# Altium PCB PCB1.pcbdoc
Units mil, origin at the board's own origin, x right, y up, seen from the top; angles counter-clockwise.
Board outline 4493.1 x 3021.15 mil, 2 copper layers (Top Layer, Bottom Layer); 85 components, 97 nets, 410 pads, 224 vias.
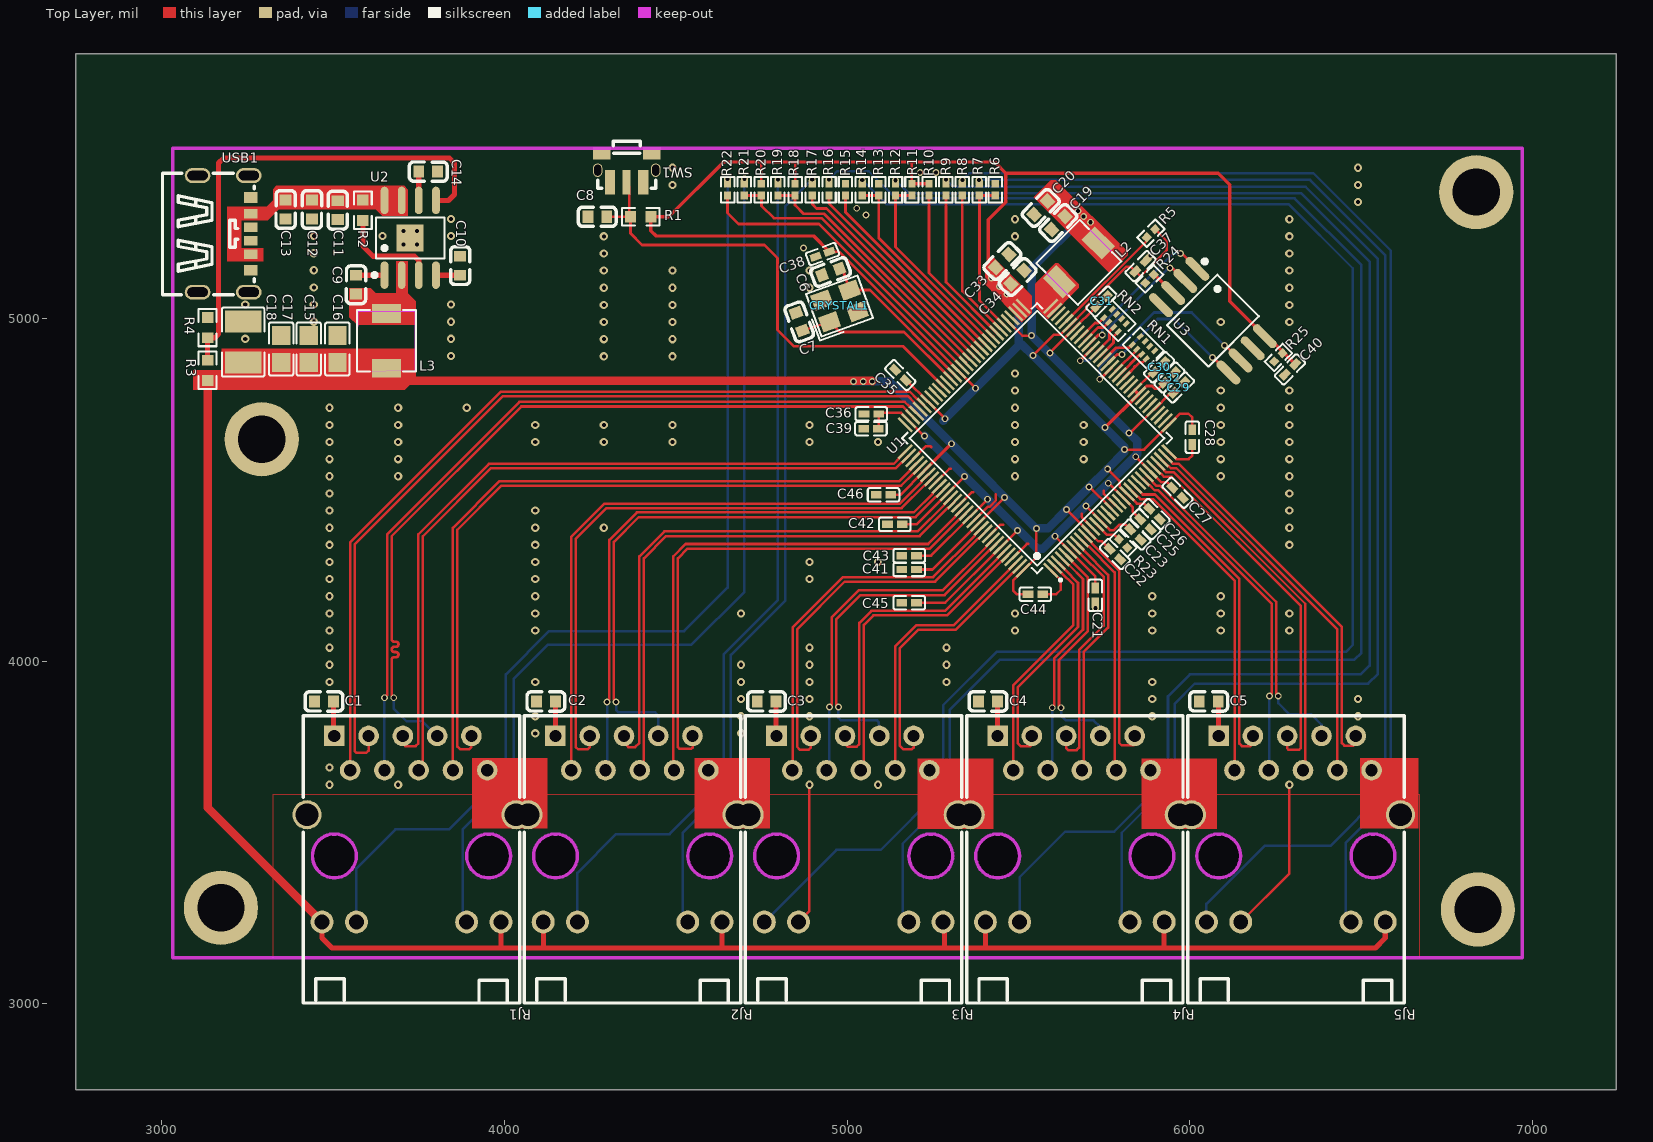
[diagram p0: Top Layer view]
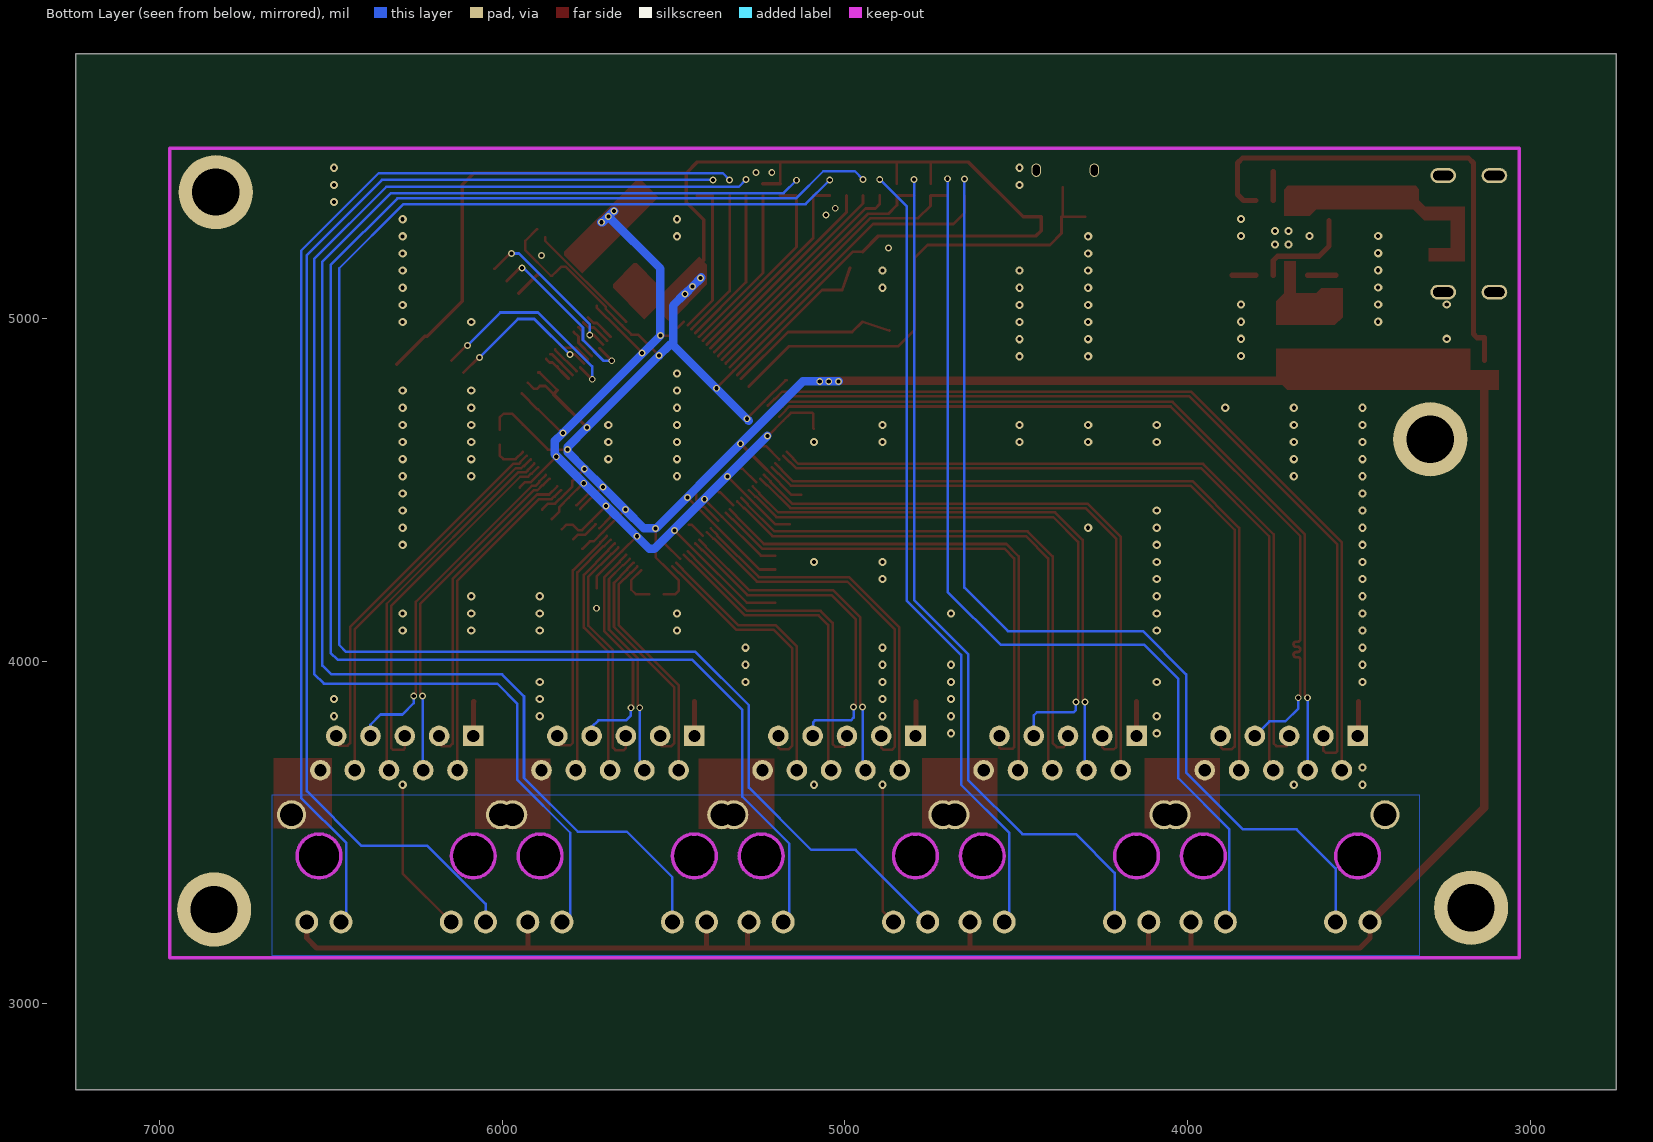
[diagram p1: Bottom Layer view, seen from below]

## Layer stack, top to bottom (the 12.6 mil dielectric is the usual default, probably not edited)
Top Layer: signal copper (thickness not stored)
Dielectric: dielectric 12.6, FR-4, Dk 4.8
Bottom Layer: signal copper (thickness not stored)

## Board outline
7243.1,2750 2750,2750 2750,5771.15 7243.1,5771.15

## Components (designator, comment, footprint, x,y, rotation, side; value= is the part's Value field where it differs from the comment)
C1 "CAP_0603" C0603 3473.85,3882.04 r0 top
C2 "CAP_0603" C0603 4121.23,3882.04 r0 top
C3 "CAP_0603" C0603 4764.99,3882.04 r0 top
C4 "CAP_0603" C0603 5410.99,3882.04 r0 top
C5 "CAP_0603" C0603 6054.99,3882.04 r0 top
C6 "CAP_0603" C0603 4951.99,5135.04 r20 top
C7 "CAP_0603" C0603 4859.99,4990.04 r110 top
C8 "CAP_0603" C0603 4270.99,5296 r0 top
C9 "CAP_0603" C0603 3567.16,5098.04 r90 top
C10 "CAP_0603" C0603 3870.84,5153.3 r270 top
C11 "CAP_0603" C0603 3513.66,5315.46 r90 top
C12 "CAP_0603" C0603 3438.72,5317.52 r90 top
C13 "CAP_0603" C0603 3361.72,5317.52 r90 top
C14 "CAP_0603" C0603 3777.55,5428.04 r180 top
C15 "CAP_0805" C0805 3429.16,4910.31 r270 top
C16 "CAP_0805" C0805 3512.7,4910.31 r270 top
C17 "CAP_0805" C0805 3348.7,4910.31 r270 top
C18 "JMK325ABJ107MM-T" C1210 3237.7,4930.68 r270 top
C19 "CAP_0603" C0603 5615.99,5278.04 r45 top
C20 "CAP_0603" C0603 5564.99,5322.04 r45 top
C21 "CAP_0402" C0402 5723.99,4191.55 r270 top
C22 "CAP_0402" C0402 5780.99,4312.04 r315 top
C23 "CAP_0402" C0402 5840.99,4369.04 r315 top
C25 "CAP_0402" C0402 5869.99,4399.21 r315 top
C26 "CAP_0402" C0402 5896.99,4429.04 r315 top
C27 "CAP_0402" C0402 5963.99,4491.04 r315 top
C28 "CAP_0402" C0402 6006.99,4653.04 r270 top
C29 "CAP_0402" C0402 5967.99,4798.04 r45 top
C30 "CAP_0402" C0402 5909.99,4857.04 r45 top
C31 "CAP_0402" C0402 5741.99,5049.04 r45 top
C32 "CAP_0402" C0402 5939.99,4827.04 r45 top
C33 "CAP_0603" C0603 5452.38,5167.04 r225 top
C34 "CAP_0603" C0603 5496.92,5120.04 r225 top
C35 "CAP_0402" C0402 5154.99,4834.04 r135 top
C36 "CAP_0402" C0402 5070.37,4721.04 r180 top
C37 "CAP_0402" C0402 5855.99,5152.04 r45 top
C38 "CAP_0402" C0402 4927.99,5187.04 r200 top
C39 "CAP_0402" C0402 5069.34,4678.04 r180 top
C40 "CAP_0402" C0402 6291.99,4851.04 r45 top
C41 "CAP_0402" C0402 5180.92,4267.04 r180 top
C42 "CAP_0402" C0402 5139.01,4398.98 r180 top
C43 "CAP_0402" C0402 5180.92,4307.57 r180 top
C44 "CAP_0402" C0402 5548.98,4195.04 r0 top
C45 "CAP_0402" C0402 5180.92,4170.04 r180 top
C46 "CAP_0402" C0402 5105.99,4485.04 r180 top
CRYSTAL1 "CF4025M00010" CRYSTAL-SMD_4P-L3.2-W2.5-BL 4977.99,5036.04 r20 top
L2 "FXL0420-2R2-M" IND-SMD_L4.4-W4.2 5675.99,5163.04 r225 top
L3 "FXL0420-2R2-M" IND-SMD_L4.4-W4.2 3655.99,4934.15 r270 top
R1 "Res_0603" R0603 4397.71,5296.11 r0 top
R2 "Res_0603" R0603 3586.96,5315.04 r90 top
R3 "Res_0603" R0603 3134.16,4848.04 r270 top
R4 "Res_0603" R0603 3134.16,4972.97 r270 top
R5 "Res_0402" R0402 5885.99,5248.04 r225 top
R6 "Res_0402" R0402 5431.99,5375.33 r270 top
R7 "Res_0402" R0402 5384.99,5375.33 r270 top
R8 "Res_0402" R0402 5335.99,5375.33 r270 top
R9 "Res_0402" R0402 5287.99,5375.33 r270 top
R10 "Res_0402" R0402 5238.99,5375.33 r270 top
R11 "Res_0402" R0402 5188.99,5375.33 r270 top
R12 "Res_0402" R0402 5140.99,5375.33 r270 top
R13 "Res_0402" R0402 5091.99,5375.33 r270 top
R14 "Res_0402" R0402 5043.99,5375.33 r270 top
R15 "Res_0402" R0402 4994.99,5375.33 r270 top
R16 "Res_0402" R0402 4946.99,5375.33 r270 top
R17 "Res_0402" R0402 4897.99,5375.33 r270 top
R18 "Res_0402" R0402 4847.99,5375.33 r270 top
R19 "Res_0402" R0402 4797.99,5375.33 r270 top
R20 "Res_0402" R0402 4748.99,5375.33 r270 top
R21 "Res_0402" R0402 4699.99,5375.33 r270 top
R22 "Res_0402" R0402 4650.99,5375.33 r270 top
R23 "Res_0402" R0402 5804.99,4343.04 r135 top
R24 "Res_0402" R0402 5881.99,5115.04 r45 top
R25 "Res_0402" R0402 6257.99,4886.04 r45 top
RJ1 "HR911130A" RJ45-TH_HR911130A 3728.99,3510.04 r180 top
RJ2 "HR911130A" RJ45-TH_HR911130A 4373.99,3510.04 r180 top
RJ3 "HR911130A" RJ45-TH_HR911130A 5018.99,3510.04 r180 top
RJ4 "HR911130A" RJ45-TH_HR911130A 5663.99,3510.04 r180 top
RJ5 "HR911130A" RJ45-TH_HR911130A 6308.99,3510.04 r180 top
RN1 "EXB28V102JX" RES-ARRAY-SMD_0402-8P-L2.0-W1.0-BL 5863.99,4914.04 r135 top
RN2 "EXB28V102JX" RES-ARRAY-SMD_0402-8P-L2.0-W1.0-BL 5781.99,4993.04 r135 top
SW1 "ST-1133" KEY-SMD_ST-1133 4356.71,5439.04 r180 top
U1 "RTL8367S-CG" LQFP-128_L14.0-W14.0-P0.40-LS16.0-BL 5553.99,4650.04 r45 top
U2 "SY8205FCC" SOIC-8_L5.0-W4.0-P1.27-LS6.0-BL-EP2.0 3725.16,5234.76 r0 top
U3 "W25Q32JVSSIQ" SOIC-8_L5.3-W5.3-P1.27-LS8.0-BL 6066.99,4993.04 r225 top
USB1 "TYPE-C 6P(073)" TYPE-C-SMD_TYPE-C-6P 3181.99,5246.23 r270 top

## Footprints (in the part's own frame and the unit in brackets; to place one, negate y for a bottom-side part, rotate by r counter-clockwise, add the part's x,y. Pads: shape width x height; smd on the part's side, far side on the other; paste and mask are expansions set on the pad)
C0402 [mm]
  rect 0.79x0.54 smd: 1(-0.545,0) 2(0.545,0)
  silkscreen extent -1.17,-0.5 1.17,0.5
C0603 [mm]
  rect 0.8x0.9 smd: 1(-0.7,0) 2(0.7,0)
  silkscreen extent -1.41,-0.71 1.39,0.72
C0805 [mm]
  rect 1.41x1.35 smd: 1(-1,0) 2(1,0)
  silkscreen extent -1.96,-0.9 1.96,0.9
C1210 [mm]
  rect 1.635x2.7 smd: 1(-1.517,0) 2(1.517,0)
  silkscreen extent -2.56,-1.58 2.56,1.58
CRYSTAL-SMD_4P-L3.2-W2.5-BL [mm]
  rect 1.4x1.2 smd: 1(-1.1,-0.85) 2(1.1,-0.85) 3(1.1,0.85) 4(-1.1,0.85)
  silkscreen extent -2.26,-1.91 2.03,1.68
IND-SMD_L4.4-W4.2 [mm]
  rect 1.4x2.12 smd: 1(2.028,0) 2(-2.028,0)
  silkscreen extent -2.28,-2.18 2.28,2.18
KEY-SMD_ST-1133 [mm]
  oval 0.7x1 hole 0.5 slot 0.8 at 90 deg: 1(-2.15,0.175) 3(2.15,0.175)
  rect 1.3x0.9 smd: 1(-1.85,-1.075) 3(1.85,-1.075)
  rect 0.75x1.8 smd: 1(-1.225,1.075) 3(1.225,1.075)
  rect 0.6x1.8 smd: 2(0,1.075)
  silkscreen extent -2.16,-1.96 2.16,1.52
LQFP-128_L14.0-W14.0-P0.40-LS16.0-BL [mm]
  rect 0.2x1.46 smd: 1(-6.2,-7.63) 2(-5.8,-7.63) 3(-5.4,-7.63) 4(-5,-7.63) 5(-4.6,-7.63) 6(-4.2,-7.63) 7(-3.8,-7.63) 8(-3.4,-7.63) 9(-3,-7.63) 10(-2.6,-7.63) 11(-2.2,-7.63) 12(-1.8,-7.63) 13(-1.4,-7.63) 14(-1,-7.63) 15(-0.6,-7.63) 16(-0.2,-7.63) 17(0.2,-7.63) 18(0.6,-7.63) 19(1,-7.63) 20(1.4,-7.63) 21(1.8,-7.63) 22(2.2,-7.63) 23(2.6,-7.63) 24(3,-7.63) 25(3.4,-7.63) 26(3.8,-7.63) 27(4.2,-7.63) 28(4.6,-7.63) 29(5,-7.63) 30(5.4,-7.63) 31(5.8,-7.63) 32(6.2,-7.63) 65(6.2,7.63) 66(5.8,7.63) 67(5.4,7.63) 68(5,7.63) 69(4.6,7.63) 70(4.2,7.63) 71(3.8,7.63) 72(3.4,7.63) 73(3,7.63) 74(2.6,7.63) 75(2.2,7.63) 76(1.8,7.63) 77(1.4,7.63) 78(1,7.63) 79(0.6,7.63) 80(0.2,7.63) 81(-0.2,7.63) 82(-0.6,7.63) 83(-1,7.63) 84(-1.4,7.63) 85(-1.8,7.63) 86(-2.2,7.63) 87(-2.6,7.63) 88(-3,7.63) 89(-3.4,7.63) 90(-3.8,7.63) 91(-4.2,7.63) 92(-4.6,7.63) 93(-5,7.63) 94(-5.4,7.63) 95(-5.8,7.63) 96(-6.2,7.63)
  rect 1.46x0.2 smd: 33(7.63,-6.2) 34(7.63,-5.8) 35(7.63,-5.4) 36(7.63,-5) 37(7.63,-4.6) 38(7.63,-4.2) 39(7.63,-3.8) 40(7.63,-3.4) 41(7.63,-3) 42(7.63,-2.6) 43(7.63,-2.2) 44(7.63,-1.8) 45(7.63,-1.4) 46(7.63,-1) 47(7.63,-0.6) 48(7.63,-0.2) 49(7.63,0.2) 50(7.63,0.6) 51(7.63,1) 52(7.63,1.4) 53(7.63,1.8) 54(7.63,2.2) 55(7.63,2.6) 56(7.63,3) 57(7.63,3.4) 58(7.63,3.8) 59(7.63,4.2) 60(7.63,4.6) 61(7.63,5) 62(7.63,5.4) 63(7.63,5.8) 64(7.63,6.2) 97(-7.63,6.2) 98(-7.63,5.8) 99(-7.63,5.4) 100(-7.63,5) 101(-7.63,4.6) 102(-7.63,4.2) 103(-7.63,3.8) 104(-7.63,3.4) 105(-7.63,3) 106(-7.63,2.6) 107(-7.63,2.2) 108(-7.63,1.8) 109(-7.63,1.4) 110(-7.63,1) 111(-7.63,0.6) 112(-7.63,0.2) 113(-7.63,-0.2) 114(-7.63,-0.6) 115(-7.63,-1) 116(-7.63,-1.4) 117(-7.63,-1.8) 118(-7.63,-2.2) 119(-7.63,-2.6) 120(-7.63,-3) 121(-7.63,-3.4) 122(-7.63,-3.8) 123(-7.63,-4.2) 124(-7.63,-4.6) 125(-7.63,-5) 126(-7.63,-5.4) 127(-7.63,-5.8) 128(-7.63,-6.2)
  silkscreen extent -7.08,-8.76 7.08,7.08
R0402 [mm]
  rect 0.566x0.54 smd: 1(-0.433,0) 2(0.433,0)
  silkscreen extent -0.94,-0.5 0.94,0.5
R0603 [mil]
  rect 31.75x34.02 smd: 1(-29.66,0) 2(29.66,0)
  silkscreen extent -55,-26 55,26
RES-ARRAY-SMD_0402-8P-L2.0-W1.0-BL [mm]
  rect 0.3x0.505 smd: 1(-0.75,0.427) 2(-0.25,0.427) 3(0.25,0.427) 4(0.75,0.427) 5(0.75,-0.427) 6(0.25,-0.427) 7(-0.25,-0.427) 8(-0.75,-0.427)
  silkscreen extent -1.23,-0.91 1.23,0.91
RJ45-TH_HR911130A [mil]
  round 66.93 hole 43.31: 11(260.83,271.46) 12(160.83,271.46) 13(-160.83,271.46) 14(-260.83,271.46)
  rect 60x60 hole 35.83: P1(225.2,-271.45)
  round 60 hole 35.83: P2(179.1,-171.45) P3(125.2,-271.45) P4(79.1,-171.45) P5(25.2,-271.45) P6(-20.9,-171.45) P7(-74.8,-271.45) P8(-120.9,-171.45) P9(-174.8,-271.45) P10(-220.9,-171.45)
  round 85 hole 66.93: SHIELD0(-304.92,-41.55) SHIELD1(304.92,-41.55)
  Multi-Layer board cut-out: -288.98,78.55 -282.64,50.79 -264.89,28.53 -239.24,16.17 -210.76,16.17 -185.11,28.53 -167.36,50.79 -161.02,78.55 -161.02,78.55 -167.36,106.3 -185.11,128.56 -210.76,140.92 -239.24,140.92 -264.89,128.56 -282.64,106.3 -288.98,78.55
  Multi-Layer board cut-out: 161.02,78.55 167.36,50.79 185.11,28.53 210.76,16.17 239.24,16.17 264.89,28.53 282.64,50.79 288.98,78.55 288.98,78.55 282.64,106.3 264.89,128.56 239.24,140.92 210.76,140.92 185.11,128.56 167.36,106.3 161.02,78.55
  silkscreen extent -316,-331 316,508
SOIC-8_L5.0-W4.0-P1.27-LS6.0-BL-EP2.0 [mm]
  oval 0.574x2.038 smd: 1(-1.905,-2.769) 2(-0.635,-2.769) 3(0.635,-2.769) 4(1.905,-2.769) 5(1.905,2.769) 6(0.635,2.769) 7(-0.635,2.769) 8(-1.905,2.769)
  rect 2x2 smd: 9(0,0)
  silkscreen extent -2.79,-2.92 2.53,1.52
SOIC-8_L5.3-W5.3-P1.27-LS8.0-BL [mm]
  oval 0.63x2.25 smd: 1(-1.905,-3.53) 2(-0.635,-3.53) 3(0.635,-3.53) 4(1.905,-3.53) 5(1.905,3.53) 6(0.635,3.53) 7(-0.635,3.53) 8(-1.905,3.53)
  silkscreen extent -2.82,-3.68 2.64,2.18
TYPE-C-SMD_TYPE-C-6P [mm]
  oval 1.1x1.9 hole 0.7 slot 1.5 at 90 deg: 7(-4.32,-1.963) 7(-4.32,1.838) 7(4.32,-1.963) 7(4.32,1.838)
  rect 0.7x1 smd: A5(-0.5,1.963) A9(1.5,1.963) B5(0.5,1.963) B9(-1.5,1.963)
  rect 0.8x1 smd: A12(2.7,1.963) B12(-2.7,1.963)
  silkscreen extent -4.5,-4.56 4.5,2.24

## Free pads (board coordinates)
  round 216.54 hole 137.8: 1(3172.99,3280.04) 1(3291.99,4647.04) 1(6834.99,5368.04) 1(6839.99,3275.04)

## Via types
v1: diameter 24, hole 12, Top Layer to Bottom Layer, 158 vias
v2: diameter 20, hole 12, Top Layer to Bottom Layer, 65 vias
v3: diameter 20, hole 12.01, Top Layer to Bottom Layer, 1 vias

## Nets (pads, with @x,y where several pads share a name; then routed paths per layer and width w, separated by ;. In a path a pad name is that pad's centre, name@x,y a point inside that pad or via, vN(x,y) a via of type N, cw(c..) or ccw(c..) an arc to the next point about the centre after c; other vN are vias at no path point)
1V1: C19.2 C20.2 C21.1 C23.1 C25.1 C27.1 C29.1 C31.1 C36.1 C39.1 C42.1 C43.1 C45.1 L2.2 U1.6 U1.14 U1.20 U1.27 U1.37 U1.58 U1.69 U1.95 U1.108 U1.114 U1.122 | length 4007.2
  Top Layer w7.4: C39.1 5091.83,4679.06 C36.1 5094.83,4724.04 5157.05,4724.04 U1.95 5223.99,4657.1 v2@5223.99,4655.04 ; C42.1 5202.71,4398.98 U1.108 v2(5341.76,4538.04) v2@5341.99,4538.04 ; C45.1 5285.57,4170.04 U1.122 5447.79,4331.84 v2(5496.99,4381.04) ; C43.1 5244.92,4307.57 U1.114 5408.99,4471.63 v2(5408.99,4472.04) ; U1.69 5511.1,4949.04 v2@5535.99,4949.04 ; v2(5591.99,4899.04) 5591.99,4899.62 U1.58 5723.93,5031.57 C31.1@5723.93,5035.86 ; v2(5605.99,4364.04) 5606.15,4364.04 U1.6 5723.99,4246.2 C21.1 ; v2(5696.99,4452.04) 5738.56,4410.47 U1.14 5766.31,4382.04 5777.99,4382.04 5793.99,4398.04 5811.99,4398.04 C23.1 ; v2@5761.99,4519.04 5762.94,4519.04 U1.20 5832.99,4448.99 5832.99,4436.21 C25.1 ; v2@5824.99,4665.04 5825.1,4665.04 U1.37 5896.01,4734.39 C29.1@5942.13,4780.51 ; v2(5841.99,4596.04) 5841.99,4595.88 U1.27 5915.66,4522.2 5932.82,4522.2 C27.1
  Bottom Layer w25: v2(5225.99,4657.04) 5555.99,4327.04 5569.99,4327.04 v2(5761.68,4518.73) 5845.99,4603.04 5845.99,4642.04 v2(5822.38,4665.64) v2(5537.99,4950.04) 5537.99,5145.04 v2(5689.99,5297.04) ; v2@5672.99,5312.84 5674.19,5312.84 v2(5689.99,5297.04) ; v2(5709.99,5280.04) 5706.99,5280.04 v2(5689.99,5297.04)
  other v2: 5672.99,5313.04
3V3: C15.2 C16.2 C17.2 C18.2 C22.1 C26.1 C28.1 C30.1 C32.1 C33.2 C34.2 C35.1 C37.1 C38.1 C40.2 C41.1 C44.1 C46.1 L3.1 R1.2 R3.2 R5.1 R10.1 R11.1 R18.1 R20.1 R25.2 RJ1.11 RJ1.14 RJ2.11 RJ2.14 RJ3.14 RJ4.11 RJ4.14 RJ5.14 U1.11 U1.17 U1.21 U1.33 U1.41 U1.42 U1.59 U1.65 U1.66 U1.67 U1.82 U1.90 U1.102 U1.116 U1.128 U3.8 | length 15641.1
  Top Layer w7.4: 4748.27,5456.04 4748.99,5455.32 R20.1 ; R18.1 4847.99,5455.69 4848.33,5456.04 ; C38.1 4976.65,5194.38 5324.88,4846.15 U1.82 5373.99,4796.63 v2(5373.99,4796.04) ; C46.1 5155.15,4485.04 U1.102 ; C35.1 5173.58,4818.86 U1.90 5284.99,4707.46 v2(5284.99,4707.04) ; 5188.63,5456.04 5188.99,5455.68 R11.1 ; C41.1 5248.94,4267.04 U1.116 ; U1.116 v2(5458.99,4477.04) ; C44.1 5494.39,4195.04 5484.99,4204.44 5484.99,4235.84 U1.128 5551.99,4302.84 v2(5551.99,4387.04) ; v2@5543.99,4893.04 5603.51,4952.56 5622.67,4952.56 U1.59 5697.99,5027.88 5697.99,5034.03 5813.99,5150.04 5827.64,5150.04 C37.1 5853.64,5124.04 5857.99,5124.04 5931.99,5198.04 5931.99,5226.13 R5.1 ; v2(5639.99,4442.04) 5639.99,4441.55 U1.11 5732.5,4349.04 5743.99,4349.04 C22.1 ; v2(5705.99,4508.04) 5707.12,4508.04 U1.17 ; v2(5759.99,4560.04) 5794.75,4525.27 5794.75,4509.49 U1.21 5845.21,4459.04 5865.95,4459.04 C26.1@5882.84,4442.14 ; v2(5808.99,4617.04) 5866.18,4617.04 U1.33 5971.18,4722.04 5994.99,4722.04 6006.99,4710.04 C28.1 ; U1.42 5890.57,4841.86 C30.1 ; U1.41 5873.42,4802.44 5889.59,4802.44 5896.99,4795.04 5907.99,4795.04 C32.1
  Top Layer w10: C38.1 4902.49,5240.04 4442.99,5240.04 4427.37,5255.65 R1.2 4480.06,5296.11 4639.99,5456.04 4748.27,5456.04 4848.33,5456.04 5188.63,5456.04 5429.99,5456.04 5462.99,5423.04 ; R11.1 R10.1 ; U1.102@5227.5,4557.55 5300.99,4631.04 v2@5301.15,4631.04 ; C33.2 5410.99,5169.45 5410.99,5287.04 5462.99,5339.04 5462.99,5423.04 ; v2(5751.99,4681.04) U1.41 U1.42 ; C40.2 6225.58,4947.8 U3.8 6115.99,5050.1 6115.99,5389.04 6081.99,5423.04 5462.99,5423.04
  Top Layer w15: RJ1.11 3468.16,3191.87 3496.99,3163.04 3989.82,3163.04 ; RJ1.14 3989.82,3163.04 ; RJ2.11 4113.56,3238.18 4113.56,3163.04 ; RJ2.14 4634.82,3163.82 4634.03,3163.04 ; RJ3.14 5284.22,3234.17 5284.22,3163.04 ; RJ4.11 5403.16,3168.02 5408.14,3163.04 ; RJ4.14 5924.82,3164.49 5923.36,3163.04 ; RJ5.14 6569.82,3191.87 6540.99,3163.04 5923.36,3163.04 ; 3989.82,3163.04 4113.56,3163.04 ; 4113.56,3163.04 4634.03,3163.04 ; 4634.03,3163.04 5284.22,3163.04 ; 5284.22,3163.04 5408.14,3163.04 ; 5408.14,3163.04 5923.36,3163.04
  Top Layer w25: R3.2 3134.16,3572.58 RJ1.11 ; 3659.99,4818.04 5070.99,4818.04 v2(5072.99,4816.04)
  Bottom Layer w7.4: v2@5284.99,4706.04 v2(5284.99,4707.04) ; v2(5458.99,4477.04) v2@5459.98,4478.03 ; v2(5639.99,4442.04) 5640.33,4441.69 v2@5640.33,4441.38 ; v2(5705.99,4508.04) v2@5706.48,4507.55 ; v2@5759.35,4560.4 5759.62,4560.4 v2(5759.99,4560.04)
  Bottom Layer w25: v2(5018.37,4816.04) v2(5046.99,4816.04) v2(5072.99,4816.04) 5121.99,4816.04 v2(5303.99,4634.04) 5550.99,4387.04 v2(5551.99,4387.04) 5585.99,4387.04 5640.33,4441.38 5706.49,4507.54 5759.35,4560.4 5807.99,4609.04 5807.99,4625.04 v2(5751.99,4681.04) v2(5541.71,4891.31) 5510.99,4922.04 5500.99,4922.04 ; v2@5279.99,4701.04 5284.99,4706.04 5500.99,4922.04 ; v2@5418.99,5119.04 5418.99,5118.04 v2(5443.99,5093.04) 5465.75,5071.27 v2(5466.75,5071.27) 5500.99,5037.04 5500.99,4922.04
  other v2: 5420.99,5117.04
$1N2235: R8.2 U1.71 | length 436.2
  Top Layer w8: R8.2 5335.99,5079.62 U1.71
$1N2238: R9.2 U1.72 | length 462.6
  Top Layer w8: R9.2 5287.99,5105.34 U1.72
$1N2241: R10.2 U1.73 | length 489.4
  Top Layer w8: R10.2 5238.99,5132.07 U1.73
$1N2244: R11.2 R12.2 U1.74 | length 584.5
  Top Layer w8: R11.2 R12.2 5140.99,5208.04 5413.96,4935.06 U1.74
$1N2247: R13.2 R14.2 U1.75 | length 611.4
  Top Layer w8: R14.2 R13.2 5091.99,5234.52 U1.75
$1N2250: R15.2 U1.76 | length 610.1
  Top Layer w8: R15.2 4994.99,5309.26 U1.76
$1N2253: R16.2 U1.77 | length 636.5
  Top Layer w8: R16.2 4946.99,5334.99 U1.77
$1N2256: R17.2 U1.78 | length 680.1
  Top Layer w8: R17.2 4897.99,5333.04 4910.99,5320.04 4939.66,5320.04 U1.78
$1N2259: R18.2 R19.2 U1.79 | length 775.3
  Top Layer w8: R19.2 R18.2 4847.99,5330.04 4872.99,5305.04 4932.39,5305.04 U1.79
$1N2262: R20.2 R21.2 U1.80 | length 868.5
  Top Layer w8: R21.2 R20.2 4749.99,5357.29 4749.99,5328.04 4785.99,5292.04 4924.99,5292.04 5347.14,4869.88 U1.80
$1N2265: R22.2 U1.81 | length 922.7
  Top Layer w8: R22.2 4650.99,5307.04 4682.99,5275.04 4917.86,5275.04 U1.81
$1N2660: C1.2 RJ1.P1 | length 101.5
  Top Layer w15: C1.2 3501.41,3783.86 RJ1.P1
$1N2849: C2.2 RJ2.P1 | length 100.5
  Top Layer w15: RJ2.P1 C2.2
$1N3010: C3.2 RJ3.P1 | length 101.1
  Top Layer w15: C3.2 4792.55,3782.73 RJ3.P1
$1N3171: C4.2 RJ4.P1 | length 100.6
  Top Layer w15: C4.2 5438.79,3881.8 RJ4.P1
$1N3560: C5.2 RJ5.P1 | length 101.1
  Top Layer w15: C5.2 6083.79,3880.8 RJ5.P1
$1N4391: C9.2 U2.1 | length 83.1
  Top Layer w15: C9.2 3650.03,5125.6 U2.1
$1N4398: C9.1 L3.2 U2.2
$1N4427: C10.2 U2.4 | length 70.7
  Top Layer w15: U2.4 C10.2
$1N4679: C14.2 U2.6 | length 84.3
  Top Layer w15: C14.2 3750.16,5427.87 U2.6
$1N5030: R2.1 U2.3 | length 298.1
  Top Layer w15: 3586.96,5211.07 R2.1 ; 3586.99,5211.04 3616.99,5181.04 3737.99,5181.04 3750.16,5168.86 U2.3
$1N6256: RN1.1 U1.45 | length 91.5
  Top Layer w8: U1.45 5852.94,4871.04 5860.99,4871.04 RN1.1@5871.2,4881.25 ; 5838.2,4859.25 5839.97,4859.25
$1N6270: RN1.2 U1.46 | length 89.9
  Top Layer w8: U1.46 5854.81,4895.18 RN1.2
$1N6372: RN1.3 U1.47 | length 89
  Top Layer w8: U1.47 5845.13,4907.77 RN1.3
$1N6383: RN1.4 U1.50 | length 99.7
  Top Layer w8: U1.50 5784.58,4914.04 5822.22,4914.04 RN1.4
$1N6394: RN2.1 U1.51 | length 91.7
  Top Layer w8: U1.51 5777,4928.73 5777,4946.29 RN2.1
$1N6399: RN2.2 U1.52 | length 93.3
  Top Layer w8: U1.52 5764.99,4938.99 5764.99,4962.12 RN2.2
$1N6404: RN2.3 U1.55 | length 91.2
  Top Layer w8: U1.55 5732.23,4973.04 5748.07,4973.04 RN2.3
$1N6415: RN2.4 U1.56 | length 89.5
  Top Layer w8: U1.56 5722.95,4986.04 5733.22,4986.04 RN2.4
$1N9315: R6.2 R7.2 U1.70 | length 456.4
  Top Layer w8: R6.2 R7.2 5386.24,5357.04 5386.24,5051.62 U1.70
$1N12059: R24.2 U3.3 | length 79.1
  Top Layer w10: R24.2 5897.58,5127.09 U3.3
EN_SWR: R5.2 U1.60 | length 343.1
  Top Layer w7.4: U1.60 5873.94,5226.1 R5.2
FB: R3.1 R4.2 U2.5 | length 1454.3
  Top Layer w15: R3.1 R4.2 3155.26,4943.31 3165.99,4954.04 3165.99,5453.04 3180.99,5468.04 3838.99,5468.04 3853.99,5453.04 3853.99,5361.04 3836.73,5343.78 U2.5
GND: C1.1 C2.1 C3.1 C4.1 C5.1 C6.1 C7.2 C8.1 C10.1 C11.1 C12.1 C13.1 C14.1 C15.1 C16.1 C17.1 C18.1 C19.1 C20.1 C21.2 C22.2 C23.2 C25.2 C26.2 C27.2 C28.2 C29.2 C30.2 C31.2 C32.2 C33.1 C34.1 C35.2 C36.2 C37.2 C38.2 C39.2 C40.1 C41.2 C42.2 C43.2 C44.2 C45.2 C46.2 CRYSTAL1.2 CRYSTAL1.4 pad.1 R4.1 R6.1 R13.1 R15.1 R23.1 R24.1 R25.1 RJ3.12 RJ5.12 RN1.5 RN1.6 RN1.7 RN1.8 RN2.5 RN2.6 RN2.7 RN2.8 SW1.1 SW1.3 U1.1 U1.12 U1.18 U1.24 U1.32 U1.34 U1.40 U1.43 U1.44 U1.57 U1.61 U1.62 U1.68 U1.85 U1.89 U1.96 U1.99 U1.105 U1.111 U1.115 U1.119 U1.125 U2.9 U3.4 U3.7 USB1.7 USB1.A12 USB1.B12 | length 1644.2
  Top Layer w7.4: RJ3.12 4889.99,3270.41 v1(4889.99,3639.04) ; U1.99 5230.32,4627.04 5242.99,4627.04 5244.99,4625.04 5244.99,4624.04 ; U1.105 5297.95,4561.04 5301.99,4561.04 ; U1.111 5363.58,4493.04 5367.99,4493.04 ; U1.115 5409.66,4450.04 5414.99,4450.04 5433.99,4469.04 5433.99,4486.04 ; U1.119 5446.74,4398.04 5455.99,4398.04 ; U1.125 5524.37,4342.04 5527.99,4342.04 ; C44.2 5609.99,4195.04 5622.99,4208.04 5622.99,4235.84 U1.1 ; 5683.99,4430.04 5683.99,4419.81 U1.12 ; 5747.99,4497.04 5747.99,4489.44 U1.18 ; U1.32 5960.18,4589.04 5995.99,4589.04 6006.99,4600.04 C28.2 ; RJ5.12 6289.99,3380.41 v1(6289.99,3639.04)
  other v1: 3489.99,3639.04 3689.99,3639.04 5089.99,3639.04 3489.99,3689.04 4089.99,3789.04 4689.99,3789.04 4089.99,3839.04 4689.99,3839.04 4889.99,3839.04 5889.99,3839.04 6489.99,3839.04 4689.99,3889.04 4889.99,3889.04 5889.99,3889.04 6489.99,3889.04 3489.99,3939.04 4089.99,3939.04 4689.99,3939.04 4889.99,3939.04 5289.99,3939.04 5889.99,3939.04 3489.99,3989.04 4689.99,3989.04 4889.99,3989.04 5289.99,3989.04 3489.99,4039.04 4889.99,4039.04 5289.99,4039.04 3489.99,4089.04 4089.99,4089.04 5489.99,4089.04 5889.99,4089.04 6089.99,4089.04 6289.99,4089.04 3489.99,4139.04 4089.99,4139.04 4689.99,4139.04 5489.99,4139.04 5889.99,4139.04 6089.99,4139.04 6289.99,4139.04 3489.99,4189.04 4089.99,4189.04 5889.99,4189.04 6089.99,4189.04 3489.99,4239.04 4089.99,4239.04 4889.99,4239.04 3489.99,4289.04 4089.99,4289.04 4889.99,4289.04 5089.99,4289.04 3489.99,4339.04 4089.99,4339.04 6289.99,4339.04 3489.99,4389.04 4089.99,4389.04 4289.99,4389.04 6289.99,4389.04 3489.99,4439.04 4089.99,4439.04 6289.99,4439.04 3489.99,4489.04 6289.99,4489.04 3489.99,4539.04 3689.99,4539.04 5489.99,4539.04 6089.99,4539.04 6289.99,4539.04 3489.99,4589.04 3689.99,4589.04 5489.99,4589.04 5689.99,4589.04 6089.99,4589.04 6289.99,4589.04 3489.99,4639.04 3689.99,4639.04 4089.99,4639.04 4289.99,4639.04 4489.99,4639.04 4889.99,4639.04 5089.99,4639.04 5489.99,4639.04 5689.99,4639.04 6089.99,4639.04 6289.99,4639.04 3489.99,4689.04 3689.99,4689.04 4089.99,4689.04 4289.99,4689.04 4489.99,4689.04 4889.99,4689.04 5489.99,4689.04 5689.99,4689.04 6089.99,4689.04 6289.99,4689.04 3489.99,4739.04 3689.99,4739.04 3889.99,4739.04 5489.99,4739.04 6089.99,4739.04 6289.99,4739.04 5489.99,4789.04 6089.99,4789.04 6289.99,4789.04 5489.99,4839.04 4289.99,4889.04 4489.99,4889.04 3843.99,4890.04 4289.99,4939.04 4489.99,4939.04 3243.99,4940.04 3843.99,4940.04 4289.99,4989.04 4489.99,4989.04 6089.99,4989.04 6289.99,4989.04 3443.99,4990.04 3843.99,4990.04 4289.99,5039.04 4489.99,5039.04 6289.99,5039.04 3243.99,5040.04 3443.99,5040.04 3843.99,5040.04 4289.99,5089.04 4489.99,5089.04 4889.99,5089.04 6289.99,5089.04 3443.99,5090.04 4289.99,5139.04 4489.99,5139.04 4889.99,5139.04 6289.99,5139.04 3443.99,5140.04 4289.99,5189.04 6289.99,5189.04 3443.99,5190.04 4289.99,5239.04 5489.99,5239.04 6289.99,5239.04 3443.99,5240.04 3643.99,5240.04 3843.99,5240.04 5489.99,5289.04 6289.99,5289.04 3843.99,5290.04 6489.99,5339.04 4489.99,5389.04 6489.99,5389.04 4489.99,5439.04 6489.99,5439.04
  other v2: 5723.99,4153.89 5884.99,5183.04 4872.99,5205.04 5054.99,5301.04 5027.99,5321.04 5212.99,5425.04 5258.99,5425.04
LAN0LED0-: R22.1 RJ1.12 | length 2939.3
  Bottom Layer w7.4: RJ1.12 3568.16,3395.29 3681.9,3509.04 3838.61,3509.04 4003.99,3674.41 4003.99,3961.04 4129.99,4087.04 4523.99,4087.04 4650.99,4214.04 v2(4650.99,5406.81)
LAN0LED1-: R21.1 RJ1.13 | length 2759.3
  Bottom Layer w7.4: RJ1.13 3877.99,3250.41 3877.99,3509.04 4026.99,3658.04 4026.99,3948.04 4125.99,4047.04 4544.99,4047.04 4699.99,4202.04 v2(4699.99,5407.03)
LAN1LED0-: R19.1 RJ2.12 | length 2500.3
  Bottom Layer w7.4: RJ2.12 4213.16,3382.21 4325.99,3495.04 4481.99,3495.04 4639.99,3653.04 4639.99,4020.04 4797.99,4178.04 v2(4797.99,5405.21)
LAN1LED1-: R17.1 RJ2.13 | length 2329.3
  Bottom Layer w7.4: RJ2.13 4519.99,3253.41 4519.99,3498.04 4660.99,3639.04 4660.99,4018.04 4819.99,4177.04 4819.99,5327.21 v2(4897.99,5405.21)
LAN2LED0+: R14.1 RJ3.11 | length 4828.9
  Bottom Layer w7.4: RJ3.11 4968.61,3449.04 5097.99,3449.04 5279.99,3631.04 5279.99,3871.04 5435.99,4027.04 6454.99,4027.04 6474.99,4047.04 6474.99,5146.04 6287.99,5333.04 5114.45,5333.04 v2(5043.99,5403.5)
LAN2LED1-: R16.1 RJ3.13 | length 4760.1
  Bottom Layer w7.4: v2(4946.99,5405.21) 4970.82,5429.04 5062.99,5429.04 5141.99,5350.04 6304.99,5350.04 6499.99,5155.04 6499.99,4024.04 6479.99,4004.04 5445.99,4004.04 5298.99,3857.04 5298.99,3604.04 5161.99,3467.04 5161.99,3256.41 RJ3.13
LAN3LED0-: R12.1 RJ4.12 | length 4206.2
  Bottom Layer w7.4: v2(5140.99,5402.72) 5178.67,5365.04 6323.99,5365.04 6523.99,5165.04 6523.99,3987.04 6497.99,3961.04 5999.99,3961.04 5935.99,3897.04 5935.99,3659.04 5778.99,3502.04 5635.99,3502.04 5503.16,3369.21 RJ4.12
LAN3LED1-: R9.1 RJ4.13 | length 3911.2
  Bottom Layer w7.4: v2(5287.99,5405.16) 5309.34,5383.8 6337.22,5383.8 6547.99,5173.04 6547.99,3962.04 6519.99,3934.04 6013.99,3934.04 5954.99,3875.04 5954.99,3653.04 5800.99,3499.04 5800.99,3254.04 5816.44,3238.58 RJ4.13
LAN4LED0+: R7.1 RJ5.11 | length 3549.7
  Bottom Layer w7.4: v2(5384.99,5403.5) 6350.52,5403.5 6569.59,5184.44 6569.59,3620.64 6409.99,3461.04 6217.99,3461.04 6048.16,3291.21 RJ5.11
LAN4LED1-: R8.1 RJ5.13 | length 3371.5
  Bottom Layer w7.4: v2(5335.99,5403.5) 5355.69,5423.2 6359.82,5423.2 6585.99,5197.04 6585.99,3601.04 6453.99,3469.04 6453.99,3254.41 RJ5.13
LX: L2.1 U1.63 U1.64
MDIREF: R23.2 U1.13 | length 83.6
  Top Layer w7.4: U1.13 5757.03,4369.04 5778.99,4369.04 R23.2
NRESET: C8.2 R1.1 SW1.2 U1.86 | length 1425.3
  Top Layer w8: C8.2 4367.94,5296 R1.1 ; SW1.2@4363.99,5381.71 4363.99,5300.17 R1.1 ; U1.86 5163.5,4918.04 4844.99,4918.04 4796.99,4966.04 4796.99,5176.04 4758.99,5214.04 4401.99,5214.04 4368.05,5247.97 R1.1
P0MDIAN: RJ1.P3 U1.92 | length 2537.5
  Top Layer w7.4: RJ1.P3 3603.99,3781.29 3603.99,3739.04 3596.99,3732.04 3568.99,3732.04 3562.99,3738.04 3562.99,4340.04 3995.59,4772.64 5176.93,4772.64 5194.57,4755 5194.57,4753.34 U1.92
P0MDIAP: RJ1.P2 U1.91 | length 2538.5
  Top Layer w7.4: RJ1.P2 3549.59,3681.79 3549.59,4345.59 3990.04,4786.04 5182.48,4786.04 5204.04,4764.48 5205.7,4764.48 U1.91
P0MDIBN: RJ1.P7 U1.94 | length 2409.6
  Top Layer w7.4: v2(3676.99,3893.04) 3670.99,3899.04 3670.99,4003.91 cw(c3678.49,4003.91) 3678.49,4011.41 3683.49,4011.41 ccw(c3683.49,4018.91) 3683.49,4026.41 3678.49,4026.41 cw(c3678.49,4033.91) 3678.49,4041.41 3683.49,4041.41 ccw(c3683.49,4048.91) 3683.49,4056.41 3678.49,4056.41 cw(c3678.49,4063.91) 3670.99,4063.91 3670.99,4364.04 4049.59,4742.64 5162.39,4742.64 5172.29,4732.73 5172.29,4731.07 U1.94
  Bottom Layer w7.4: v2(3676.99,3893.04) 3676.99,3862.04 3714.99,3824.04 3761.24,3824.04 RJ1.P7
P0MDIBP: RJ1.P4 U1.93 | length 2409.7
  Top Layer w7.4: v2(3649.99,3893.04) 3657.59,3900.64 3657.59,4369.59 4044.04,4756.04 5167.94,4756.04 5181.77,4742.2 5183.43,4742.2 U1.93
  Bottom Layer w7.4: RJ1.P4 3649.89,3892.94 v2(3649.99,3893.04)
P0MDICN: RJ1.P6 U1.98 | length 2203.1
  Top Layer w7.4: RJ1.P6 3761.99,3693.59 3761.99,4364.09 3959.94,4562.04 5141.4,4562.04 5159.5,4580.14 5161.16,4580.14 U1.98
P0MDICP: RJ1.P5 U1.97 | length 2204.2
  Top Layer w7.4: RJ1.P5 3703.79,3759.44 3711.19,3752.04 3741.19,3752.04 3748.59,3759.44 3748.59,4369.64 3954.39,4575.44 5135.85,4575.44 5150.03,4589.62 5150.03,4591.27 U1.97
P0MDIDN: RJ1.P9 U1.101 | length 2138.2
  Top Layer w7.4: RJ1.P9 3903.79,3749.44 3896.39,3742.04 3871.39,3742.04 3862.99,3750.44 3862.99,4383.04 3991.59,4511.64 5157.81,4511.64 5192.9,4546.73 5194.57,4546.73 U1.101
P0MDIDP: RJ1.P8 U1.100 | length 2139
  Top Layer w7.4: RJ1.P8 3849.59,3681.79 3849.59,4388.59 3986.04,4525.04 5152.26,4525.04 5183.43,4556.21 5183.43,4557.87 U1.100
P1MDIAN: RJ2.P3 U1.104 | length 1798.3
  Top Layer w7.4: RJ2.P3 4248.79,3748.1 4242.72,3742.04 4215.39,3742.04 4207.99,3749.44 4207.99,4356.09 4297.94,4446.04 5159.02,4446.04 5226.31,4513.33 5227.97,4513.33 U1.104
P1MDIAP: RJ2.P2 U1.103 | length 1797.7
  Top Layer w7.4: RJ2.P2 4194.59,3681.79 4194.59,4361.64 4292.39,4459.44 5153.47,4459.44 5216.83,4522.8 5216.83,4524.46 U1.103
P1MDIBN: RJ2.P7 U1.107 | length 1705.8
  Top Layer w7.4: v2(4325.76,3880.74) 4319.46,3887.04 4319.46,4347.56 4391.94,4420.04 5199.84,4420.04 5259.72,4479.92 5261.38,4479.92 U1.107
  Bottom Layer w7.4: v2(4325.76,3880.74) 4325.76,3857.44 4333.16,3850.04 4439.99,3850.04 4448.79,3841.24 RJ2.P7
P1MDIBP: RJ2.P4 U1.106 | length 1705.3
  Top Layer w7.4: v2(4299.76,3880.74) 4306.06,3887.04 4306.06,4353.11 4386.39,4433.44 5194.29,4433.44 5250.24,4489.39 5250.24,4491.05 U1.106
  Bottom Layer w7.4: RJ2.P4 4299.76,3686.37 v2(4299.76,3880.74)
P1MDICN: RJ2.P6 U1.110 | length 1598.6
  Top Layer w7.4: RJ2.P6 4406.99,3693.59 4406.99,4299.64 4471.99,4364.64 5211.25,4364.64 5293.12,4446.51 5294.78,4446.51 U1.110
P1MDICP: RJ2.P5 U1.109 | length 1599.6
  Top Layer w7.4: RJ2.P5 4348.99,3781.29 4348.99,3762.04 4361.99,3749.04 4381.59,3749.04 4393.59,3761.04 4393.59,4305.19 4466.44,4378.04 5205.7,4378.04 5283.65,4455.99 5283.65,4457.65 U1.109
P1MDIDN: RJ2.P9 U1.113 | length 1526.6
  Top Layer w7.4: RJ2.P9 4548.79,3747.84 4544.99,3744.04 4511.21,3744.04 4505.99,3749.26 4505.99,4299.64 4534.39,4328.04 5241.46,4328.04 5326.53,4413.11 5328.19,4413.11 U1.113
P1MDIDP: RJ2.P8 U1.112 | length 1526.2
  Top Layer w7.4: RJ2.P8 4492.59,3683.79 4492.59,4305.19 4528.84,4341.44 5235.91,4341.44 5317.06,4422.58 5317.06,4424.24 U1.112
P2MDIAN: RJ3.P3 U1.118 | length 1089
  Top Layer w7.4: RJ3.P3 4893.79,3747.84 4886.99,3741.04 4862.99,3741.04 4853.99,3750.04 4853.99,4092.64 4992.99,4231.64 5256.42,4231.64 5382.21,4357.43 5383.87,4357.43 U1.118
P2MDIAP: RJ3.P2 U1.117 | length 1088.9
  Top Layer w7.4: RJ3.P2 4840.59,3682.19 4840.59,4098.19 4987.44,4245.04 5250.87,4245.04 5372.74,4366.91 5372.74,4368.56 U1.117
P2MDIBN: RJ3.P7 U1.121 | length 1013.7
  Top Layer w7.4: v2(4974.29,3865.74) 4967.99,3872.04 4967.99,4121.64 5038.99,4192.64 5284.23,4192.64 5415.61,4324.02 5417.28,4324.02 U1.121
  Bottom Layer w7.4: v2(4974.29,3865.74) 4974.29,3834.74 4981.99,3827.04 5086.99,3827.04 5091.99,3822.04 5091.99,3783.29 RJ3.P7
P2MDIBP: RJ3.P4 U1.120 | length 1017.3
  Top Layer w7.4: v2(4948.29,3865.74) 4954.59,3872.04 4954.59,4127.19 5033.44,4206.04 5278.68,4206.04 5406.14,4333.5 5406.14,4335.16 U1.120
  Bottom Layer w7.4: RJ3.P4 4948.29,3689.89 v2(4948.29,3865.74)
P2MDICN: RJ3.P6 U1.124 | length 933
  Top Layer w7.4: RJ3.P6 5048.99,3690.59 5048.99,4105.64 5076.39,4133.04 5291.44,4133.04 5449.02,4290.62 5450.68,4290.62 U1.124
P2MDICP: RJ3.P5 U1.123 | length 936.1
  Top Layer w7.4: RJ3.P5 4993.79,3757.44 5001.19,3750.04 5027.69,3750.04 5035.59,3757.93 5035.59,4111.19 5070.84,4146.44 5285.89,4146.44 5439.54,4300.09 5439.54,4301.75 U1.123
P2MDIDN: RJ3.P9 U1.127 | length 814.3
  Top Layer w7.4: RJ3.P9 5193.79,3747.84 5187.99,3742.04 5163.99,3742.04 5152.99,3753.04 5152.99,4036.64 5207.99,4091.64 5316.86,4091.64 5482.43,4257.21 5484.09,4257.21 U1.127
P2MDIDP: RJ3.P8 U1.126 | length 815.6
  Top Layer w7.4: RJ3.P8 5139.59,3681.79 5139.59,4042.19 5202.44,4105.04 5311.31,4105.04 5472.95,4266.68 5472.95,4268.34 U1.126
P3MDIAN: RJ4.P3 U1.3 | length 695.3
  Top Layer w7.4: RJ4.P3 5538.79,3756.84 5532.99,3751.04 5506.86,3751.04 5497.99,3759.91 5497.99,3924.04 5673.39,4099.44 5673.39,4228.31 5635.02,4266.68 5635.02,4268.34 U1.3
P3MDIAP: RJ4.P2 U1.2 | length 691.2
  Top Layer w7.4: RJ4.P2 5484.59,3681.79 5484.59,3929.59 5659.99,4104.99 5659.99,4222.76 5625.54,4257.21 5623.88,4257.21 U1.2
P3MDIBN: RJ4.P7 U1.5 | length 686.2
  Top Layer w7.4: v2(5624.29,3863.74) 5617.99,3870.04 5617.99,4003.04 5701.39,4086.44 5701.39,4244.86 5657.29,4288.95 5657.29,4290.62 U1.5
  Bottom Layer w7.4: v2(5624.29,3863.74) 5624.29,3840.74 5637.99,3827.04 5718.99,3827.04 5738.79,3807.24 RJ4.P7
P3MDIBP: RJ4.P4 U1.4 | length 685.8
  Top Layer w7.4: v2(5598.29,3863.74) 5604.59,3870.04 5604.59,4008.59 5687.99,4091.99 5687.99,4239.31 5647.82,4279.48 5646.15,4279.48 U1.4
  Bottom Layer w7.4: RJ4.P4 5598.29,3694.89 v2(5598.29,3863.74)
P3MDICN: RJ4.P6 U1.8 | length 730.3
  Top Layer w7.4: U1.8 5690.7,4324.02 5690.7,4322.36 5761.39,4251.67 5761.39,4097.49 5689.99,4026.09 5689.99,3686.59 RJ4.P6
P3MDICP: RJ4.P5 U1.7 | length 729.5
  Top Layer w7.4: RJ4.P5 5638.79,3746.29 5644.83,3740.25 5669.19,3740.25 5676.59,3747.65 5676.59,4031.64 5747.99,4103.04 5747.99,4246.12 5681.22,4312.88 5679.56,4312.88 U1.7
P3MDIDN: RJ4.P9 U1.10 | length 718.5
  Top Layer w7.4: U1.10 5712.97,4346.29 5712.97,4344.63 5793.39,4264.22 5793.39,3761.68 5801.03,3754.04 5834.99,3754.04 5838.79,3757.84 RJ4.P9
P3MDIDP: RJ4.P8 U1.9 | length 715.8
  Top Layer w7.4: U1.9 5701.83,4335.16 5703.49,4335.16 5779.99,4258.66 5779.99,3686.39 RJ4.P8
P4MDIAN: RJ5.P3 U1.23 | length 965
  Top Layer w7.4: U1.23 5862.86,4485.92 5897.4,4485.92 6144.39,4238.93 6144.39,3759.44 6151.79,3752.04 6176.39,3752.04 6183.79,3759.44 RJ5.P3
P4MDIAP: RJ5.P2 U1.22 | length 965.7
  Top Layer w7.4: U1.22 5846.59,4479.92 5848.25,4479.92 5855.65,4472.52 5891.84,4472.52 6130.99,4233.37 6130.99,3682.59 RJ5.P2
P4MDIBN: RJ5.P7 U1.26 | length 1016.9
  Top Layer w7.4: U1.26 5891.14,4524.46 5891.14,4522.8 5902.9,4511.04 5913.37,4511.04 6251.39,4173.02 6251.39,3904.04 v2(6257.69,3897.74)
  Bottom Layer w7.4: v2(6257.69,3897.74) 6257.69,3877.34 6290.99,3844.04 6353.99,3844.04 6383.79,3814.24 RJ5.P7
P4MDIBP: RJ5.P4 U1.25 | length 1017.4
  Top Layer w7.4: U1.25 5880,4513.33 5881.66,4513.33 5897.35,4497.64 5907.82,4497.64 6237.99,4167.47 6237.99,3904.04 v2(6231.69,3897.74)
  Bottom Layer w7.4: RJ5.P4 6231.69,3683.29 v2(6231.69,3897.74)
P4MDICN: RJ5.P6 U1.29 | length 1089.8
  Top Layer w7.4: U1.29 5924.54,4557.87 5924.54,4556.21 5929.71,4551.04 5952.54,4551.04 6336.39,4167.19 6336.39,3687.99 RJ5.P6
P4MDICP: RJ5.P5 U1.28 | length 1091
  Top Layer w7.4: U1.28 5913.41,4546.73 5915.07,4546.73 5924.16,4537.64 5946.99,4537.64 6322.99,4161.64 6322.99,3745.57 6318.46,3741.04 6287.99,3741.04 6283.79,3745.24 RJ5.P5
P4MDIDN: RJ5.P9 U1.31 | length 1129.7
  Top Layer w7.4: U1.31 5946.82,4580.14 5946.82,4578.48 5949.43,4575.86 5966.14,4575.84 6442.99,4098.99 6442.99,3760.44 6450.39,3753.04 6476.39,3753.04 6483.79,3760.44 RJ5.P9
P4MDIDP: RJ5.P8 U1.30 | length 1129.8
  Top Layer w7.4: U1.30 5935.68,4569 5937.34,4569 5943.91,4562.44 5960.59,4562.44 6429.59,4093.44 6429.59,3681.79 RJ5.P8
SH_GND: RJ1.P10 RJ1.SHIELD0 RJ1.SHIELD1 RJ2.P10 RJ2.SHIELD0 RJ2.SHIELD1 RJ3.P10 RJ3.SHIELD0 RJ3.SHIELD1 RJ4.P10 RJ4.SHIELD0 RJ4.SHIELD1 RJ5.P10 RJ5.SHIELD0 RJ5.SHIELD1
SPIF_CLK: U1.48 U3.6 | length 620.4
  Top Layer w8: v2(5736.99,4822.04) 5737.12,4822.04 U1.48 ; v2(6100.99,4921.04) 6103.63,4921.04 U3.6
  Bottom Layer w8: v2(5736.99,4822.04) 5736.99,4859.04 5894.99,5017.04 6004.99,5017.04 v2(6100.99,4921.04)
SPIF_CS: U1.54 U3.1 | length 463.2
  Top Layer w8: U1.54 5732.5,4951.04 v3(5743.99,4951.04) ; v2(5971.99,5189.04) 5977.05,5189.04 U3.1
  Bottom Layer w8: v3(5743.99,4951.04) 5743.99,4982.04 5950.99,5189.04 v2(5971.99,5189.04)
SPIF_D0: U1.49 U3.5 | length 470
  Top Layer w8: U1.49 5786.86,4894.04 v2(5801.99,4894.04) ; v2(6065.99,4886.04) 6067.92,4886.04 U3.5
  Bottom Layer w8: v2(5801.99,4894.04) 5905.99,4998.04 5953.99,4998.04 v2(6065.99,4886.04)
SPIF_D1: U1.53 U3.2 | length 507.6
  Top Layer w8: v2(5679.99,4876.04) 5679.99,4876.26 U1.53 ; v2(5941.99,5147.04) 5948.34,5147.04 U3.2
  Bottom Layer w8: v2(5679.99,4876.04) 5703.99,4876.04 5763.99,4936.04 5763.99,4973.04 5937.99,5147.04 v2(5941.99,5147.04)
VBUS: C11.2 C12.2 C13.2 R2.2 U2.7 U2.8 USB1.A9 USB1.B9
XTALI: C7.1 CRYSTAL1.1 U1.84 | length 506.1
  Top Layer w8: C7.1 CRYSTAL1.1 4978.47,4960.04 5166.03,4960.04 U1.84
XTALO: C6.2 CRYSTAL1.3 U1.83 | length 478
  Top Layer w8: C6.2@4984.76,5147.46 CRYSTAL1.3 5066.05,5082.3 U1.83
pads on no net: U1.15 U1.16 U1.19 U1.35 U1.36 U1.38 U1.39 U1.87 U1.88 USB1.A5 USB1.B5
copper on no net:
  other v1: 3705.48,5215.07 3744.85,5215.07 3705.48,5254.44 3744.85,5254.44

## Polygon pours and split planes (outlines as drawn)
SH_GND on Top Layer (solid, remove dead copper, pour order 0): 3323.99,3135.04 6669.99,3135.04 6669.99,3610.04 3323.99,3610.04
SH_GND on Bottom Layer (solid, remove dead copper, pour order 6): 3323.99,3139.54 6669.99,3139.54 6669.99,3610.54 3323.99,3610.54
GND on Top Layer (solid, remove dead copper, pour order 4): 3031.99,3133.83 6968.99,3133.83 6968.99,5496.04 3031.99,5496.04
GND on Bottom Layer (solid, remove dead copper, pour order 10): 3031.99,3133.83 6968.99,3133.83 6968.99,5496.04 3031.99,5496.04

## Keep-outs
Top Layer:
  region: 5552.04,5160.25 5678.77,5286.99 5799.94,5165.82 5673.2,5039.09
  region: 3570.31,4844.53 3573.31,5020.76 3738.66,5020.76 3738.66,4847.53
Board Outline Layer:
  lines w10: 3031.99,3133.83 6968.99,3133.83 6968.99,5496.04 3031.99,5496.04 3031.99,3133.83
Multi-Layer:
  circle w10: c3953.99,3431.49 r63.98
  circle w10: c3503.99,3431.49 r63.98
  circle w10: c4598.99,3431.49 r63.98
  circle w10: c4148.99,3431.49 r63.98
  circle w10: c5243.99,3431.49 r63.98
  circle w10: c4793.99,3431.49 r63.98
  circle w10: c5888.99,3431.49 r63.98
  circle w10: c5438.99,3431.49 r63.98
  circle w10: c6533.99,3431.49 r63.98
  circle w10: c6083.99,3431.49 r63.98

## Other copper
Top Layer:
  region net SH_GND: 3905.99,3512.04 4124.99,3512.04 4124.99,3716.04 3905.99,3716.04
  region net SH_GND: 4555.49,3512.04 4774.49,3512.04 4774.49,3716.04 4555.49,3716.04
  region net SH_GND: 5206.49,3511.04 5425.49,3511.04 5425.49,3715.04 5206.49,3715.04
  region net SH_GND: 5859.37,3511.04 6078.37,3511.04 6078.37,3715.04 5859.37,3715.04
  region net SH_GND: 6497.49,3512.04 6665.49,3512.04 6665.49,3716.04 6497.49,3716.04
  region net $1N4398: 3547.99,5088.04 3547.99,5003.56 3570.31,4981.23 3741.66,4981.23 3741.66,5050.04 3718.43,5073.27 3718.43,5166.83 3683.99,5166.83 3683.99,5073.04 3624.99,5073.04 3609.99,5088.04
  region net 3V3: 3091.76,4848.04 3175.55,4848.04 3175.55,4911.37 3741.66,4911.37 3741.66,4825.04 3708.66,4792.04 3091.99,4792.04 3091.76,4792.27
  region net VBUS: 3231.99,5204.04 3296.99,5204.04 3296.99,5166.04 3191.99,5166.04 3191.99,5326.04 3306.99,5326.04 3324.99,5344.04 3324.99,5376.04 3334.99,5386.04 3707.99,5386.04 3718.43,5375.6 3718.43,5298.72 3643.31,5298.72 3623.99,5318.04 3341.36,5318.04 3309.36,5286.04 3231.99,5286.04
  region net LX: 5606.99,5160.04 5547.99,5101.04 5547.99,5034.05 5584.64,4997.4 5675.99,5088.75 5675.99,5099.34 5615.29,5160.04
  region net 1V1: 5543.99,5353.04 5765.36,5131.66 5765.78,5131.66 5817.99,5183.87 5817.99,5194.04 5608.99,5403.04 5593.99,5403.04
  region net 3V3: 5424.81,5179 5538.01,5065.79 5538.01,5015.02 5509.63,4987.69 5402.54,5098.93 5402.54,5156.73

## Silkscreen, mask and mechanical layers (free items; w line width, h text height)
Top Solder Mask Layer:
  text "RTL8367S" at 6318.24,5136.68 h77.88
  text "千兆交换机" at 6322.82,5017.12 h135.94
  text "小李工作站作品" at 6901.91,3404.55 h135.94 r90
